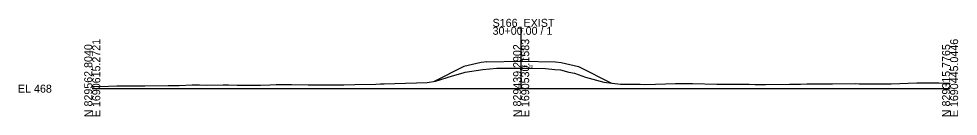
# Model space of a CAD drawing. Extents: x 1621104 to 1621433, y 1192880 to 1199414.
# Drawn here: x 1621104.2 to 1621432.7, y 1195879.5 to 1195913.8 of the extents above; entities that cross this region are included whole.
import ezdxf

# ---------------------------------------------------------------- set-up
doc = ezdxf.new("R2010")
doc.units = 0
for name, color, linetype in [('RD_GPK_XS_Cell', 7, 'Continuous'), ('RD_XS_EarthShd', 7, 'Continuous'), ('RD_XS_ExGround', 7, 'Continuous'), ('RD_XS_Pave', 7, 'Continuous'), ('RD_XS_TieSlope', 7, 'Continuous'), ('RD_XS_TX_Elev_EX', 7, 'Continuous'), ('RD_XS_TX_Elev_PR', 7, 'Continuous')]:
    doc.layers.add(name, color=color, linetype=linetype)

msp = doc.modelspace()

# ---------------------------------------------------------------- linework, layer by layer
at = {"layer": 'RD_GPK_XS_Cell'}
for p, q in [((1621279.86, 1195889.24), (1621279.86, 1195910.95)), ((1621129.86, 1195889.24), (1621279.86, 1195889.24)), ((1621279.86, 1195889.24), (1621429.86, 1195889.24))]:
    msp.add_line(p, q, dxfattribs=at)
at = {"layer": 'RD_XS_EarthShd'}
for p, q in [((1621267.86, 1195898.63), (1621265.86, 1195898.47)), ((1621291.86, 1195898.63), (1621293.86, 1195898.47))]:
    msp.add_line(p, q, dxfattribs=at)
at = {"layer": 'RD_XS_ExGround'}
msp.add_lwpolyline([(1621129.86, 1195890.05), (1621135.5, 1195890.13), (1621138.44, 1195890.2), (1621140.36, 1195890.2), (1621146.6, 1195890.29), (1621148.21, 1195890.29), (1621156.36, 1195890.31), (1621160.25, 1195890.39), (1621164.8, 1195890.6), (1621167.39, 1195890.57), (1621169.79, 1195890.48), (1621175.6, 1195890.55), (1621177.51, 1195890.56), (1621180.49, 1195890.52), (1621182.5, 1195890.49), (1621183.67, 1195890.49), (1621188.65, 1195890.47), (1621191.97, 1195890.6), (1621194.23, 1195890.66), (1621199.53, 1195890.76), (1621205.38, 1195890.64), (1621207.59, 1195890.56), (1621210.16, 1195890.56), (1621216.23, 1195890.61), (1621217.85, 1195890.62), (1621221.63, 1195890.66), (1621229.01, 1195890.79), (1621230.67, 1195890.89), (1621231.89, 1195890.92), (1621235.64, 1195891.01), (1621246.96, 1195891.37), (1621249.88, 1195891.82), (1621255.85, 1195893.73), (1621259.55, 1195894.8), (1621260.31, 1195895.08), (1621266.46, 1195895.94), (1621271.39, 1195896.44), (1621276.41, 1195896.48), (1621277.68, 1195896.47), (1621279.35, 1195896.44), (1621279.86, 1195896.43), (1621288.31, 1195896.28), (1621291.6, 1195895.96), (1621293.59, 1195895.86), (1621296.54, 1195895.04), (1621298.5, 1195894.72), (1621302.33, 1195893.24), (1621308.75, 1195891.48), (1621314.61, 1195890.85), (1621321.43, 1195890.78), (1621322.88, 1195890.73), (1621326.83, 1195890.85), (1621333.84, 1195891.08), (1621339.75, 1195891), (1621348.24, 1195890.81), (1621351.84, 1195890.81), (1621358.43, 1195890.77), (1621359.55, 1195890.77), (1621361.64, 1195890.74), (1621365.31, 1195890.71), (1621373.7, 1195890.85), (1621374.15, 1195890.85), (1621374.81, 1195890.86), (1621377.55, 1195890.86), (1621379.81, 1195890.89), (1621388.76, 1195890.98), (1621396.79, 1195891.03), (1621398.01, 1195890.99), (1621407.47, 1195890.93), (1621408.23, 1195890.94), (1621409.27, 1195890.96), (1621418.24, 1195891.25), (1621425.9, 1195891.23), (1621427.62, 1195891.22), (1621429.86, 1195891.22)], dxfattribs=at)
at = {"layer": 'RD_XS_Pave'}
for p, q in [((1621267.86, 1195898.63), (1621279.86, 1195898.87)), ((1621279.86, 1195898.87), (1621291.86, 1195898.63))]:
    msp.add_line(p, q, dxfattribs=at)
at = {"layer": 'RD_XS_TieSlope'}
for p, q in [((1621265.86, 1195898.47), (1621259.86, 1195896.97)), ((1621293.86, 1195898.47), (1621299.86, 1195896.97)), ((1621259.86, 1195896.97), (1621249.42, 1195891.75)), ((1621299.86, 1195896.97), (1621311.42, 1195891.19))]:
    msp.add_line(p, q, dxfattribs=at)

# ---------------------------------------------------------------- texts
at = {"layer": 'RD_GPK_XS_Cell'}
for s, p in [('S166_EXIST', (1621269.86, 1195910.95)), ('30+00.00 / 1', (1621269.86, 1195908.15)), ('EL 468', (1621103.86, 1195887.84))]:
    msp.add_text(s, height=2.8, dxfattribs=at).set_placement(p)
for s, p in [('N 829562.8040', (1621129.86, 1195879.24)), ('E 1690615.2721', (1621132.66, 1195879.24)), ('N 829439.2902', (1621279.86, 1195879.24)), ('E 1690530.1583', (1621282.66, 1195879.24)), ('N 829315.7765', (1621429.86, 1195879.24)), ('E 1690445.0446', (1621432.66, 1195879.24))]:
    msp.add_text(s, height=2.8, rotation=90, dxfattribs=at).set_placement(p)
at = {"layer": 'RD_XS_TX_Elev_EX'}
msp.add_text('475.20', height=1, dxfattribs=at).set_placement((1621279.76, 1195896.53))
at = {"layer": 'RD_XS_TX_Elev_PR'}
msp.add_text(' 477.63', height=1, rotation=90, dxfattribs=at).set_placement((1621280.86, 1195898.87))

doc.saveas('drawing.dxf')
